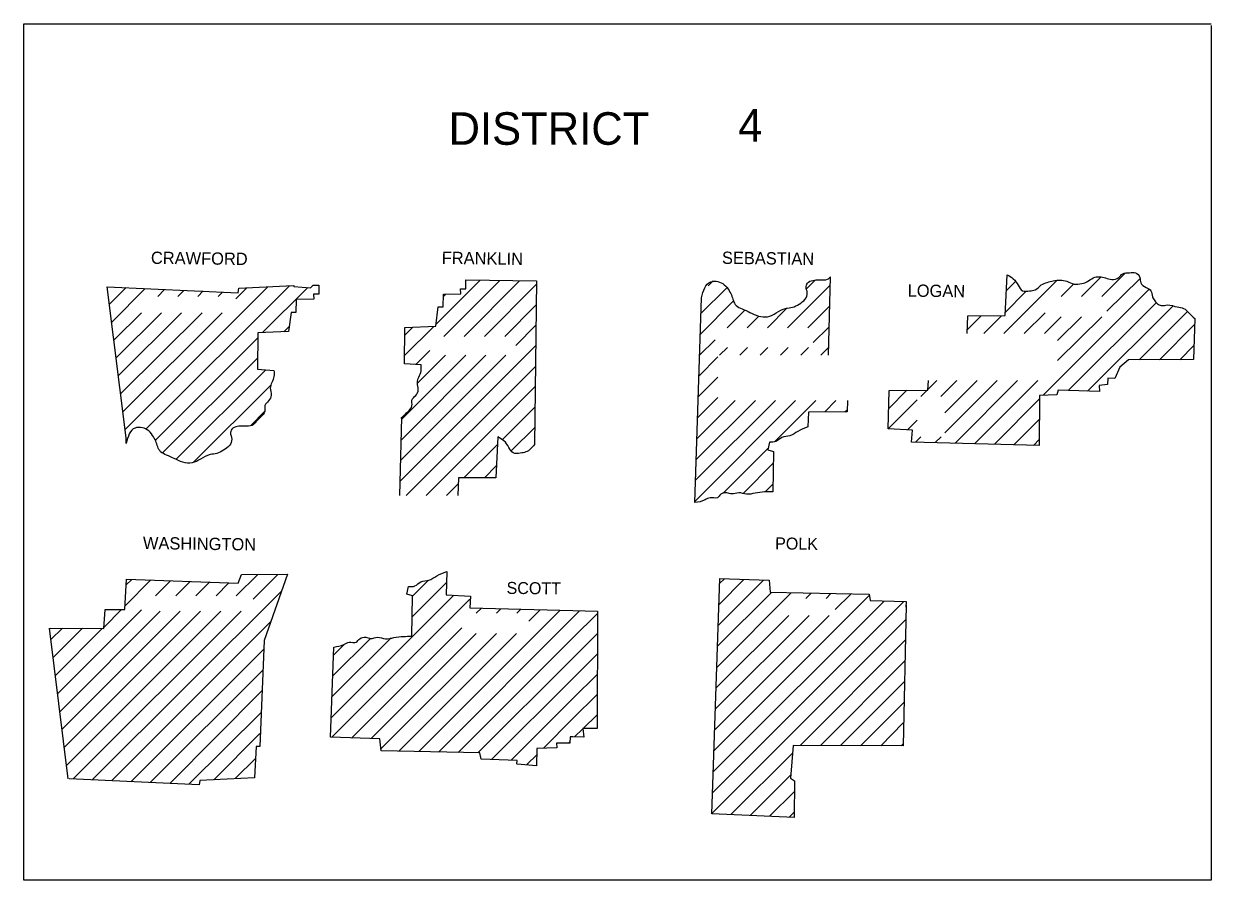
# Model space of a CAD drawing. Extents: x 21307 to 29830, y 1322443 to 1332359.
# Drawn here: x 27376.6 to 27792.3, y 1326512.9 to 1326812.9 of the extents above; entities that cross this region are included whole.
import ezdxf

# ---------------------------------------------------------------- set-up
doc = ezdxf.new("R2010")
doc.units = 0
doc.layers.add('R_Draft', color=7, linetype='Continuous')

msp = doc.modelspace()

# ---------------------------------------------------------------- linework, layer by layer
at = {"layer": 'R_Draft'}
msp.add_line((27792.32, 1326812.26), (27792.32, 1326512.86), dxfattribs=at)
for points in [[(27376.62, 1326512.86), (27376.62, 1326812.86), (27792.32, 1326812.86)], [(27658.92, 1326724.16), (27658.22, 1326696.76)], [(27706.82, 1326704.36), (27707.12, 1326710.56), (27720.12, 1326710.66), (27720.82, 1326724.96)], [(27746.92, 1326717.36), (27753.62, 1326724.06)], [(27754.02, 1326717.36), (27762.02, 1326725.36)], [(27755.82, 1326712.16), (27767.32, 1326723.56)], [(27405.82, 1326720.76), (27451.72, 1326718.66), (27451.92, 1326720.26), (27470.92, 1326721.16)], [(27412.42, 1326665.86), (27412.42, 1326667.86), (27405.82, 1326720.76)], [(27406.62, 1326714.66), (27412.42, 1326720.46)], [(27407.42, 1326708.36), (27419.12, 1326720.16)], [(27412.12, 1326670.76), (27462.12, 1326720.66)], [(27419.42, 1326670.96), (27469.62, 1326721.06)], [(27423.52, 1326717.36), (27425.92, 1326719.76)], [(27430.52, 1326717.36), (27432.62, 1326719.46)], [(27437.52, 1326717.36), (27439.42, 1326719.26)], [(27450.82, 1326716.46), (27454.62, 1326720.26)], [(27479.92, 1326721.26), (27479.92, 1326718.16), (27478.02, 1326718.16), (27478.12, 1326716.36), (27472.02, 1326716.26), (27471.92, 1326711.76), (27470.22, 1326711.76), (27469.32, 1326705.06), (27458.52, 1326704.56), (27458.42, 1326691.86), (27464.22, 1326691.46)], [(27460.22, 1326704.66), (27476.02, 1326720.46)], [(27471.12, 1326721.16), (27471.12, 1326720.86), (27477.02, 1326720.36), (27477.92, 1326721.26), (27479.92, 1326721.26)], [(27515.72, 1326693.36), (27509.92, 1326693.76), (27510.02, 1326706.46), (27520.82, 1326706.96), (27521.72, 1326713.66), (27523.42, 1326713.66), (27523.52, 1326718.16), (27529.62, 1326718.26), (27529.52, 1326720.06), (27531.42, 1326720.06), (27531.42, 1326723.16)], [(27520.92, 1326707.56), (27536.32, 1326722.96)], [(27523.72, 1326703.36), (27543.32, 1326722.96)], [(27530.82, 1326703.36), (27550.22, 1326722.76)], [(27531.42, 1326723.16), (27556.12, 1326722.76)], [(27537.92, 1326703.36), (27556.02, 1326721.56)], [(27556.12, 1326722.76), (27555.42, 1326665.46)], [(27613.52, 1326711.26), (27622.72, 1326720.36)], [(27616.22, 1326721.06), (27617.92, 1326722.76)], [(27644.02, 1326706.36), (27658.82, 1326721.16)], [(27650.62, 1326720.06), (27653.62, 1326723.06)], [(27719.72, 1326704.36), (27738.32, 1326722.96)], [(27720.52, 1326719.26), (27723.72, 1326722.46)], [(27733.52, 1326682.76), (27770.52, 1326719.76)], [(27739.82, 1326717.36), (27744.12, 1326721.66)], [(27444.72, 1326717.36), (27446.22, 1326718.86)], [(27523.42, 1326717.16), (27524.42, 1326718.16)], [(27611.52, 1326645.16), (27613.82, 1326716.86)], [(27613.42, 1326704.06), (27625.12, 1326715.76)], [(27720.12, 1326711.76), (27727.32, 1326718.96)], [(27742.22, 1326684.36), (27773.02, 1326715.16)], [(27408.22, 1326702.16), (27417.82, 1326711.66)], [(27409.02, 1326695.86), (27424.82, 1326711.66)], [(27409.72, 1326689.56), (27431.82, 1326711.66)], [(27410.52, 1326683.26), (27439.02, 1326711.66)], [(27411.32, 1326676.96), (27446.02, 1326711.66)], [(27545.02, 1326703.36), (27556.02, 1326714.36)], [(27622.82, 1326706.36), (27628.92, 1326712.46)], [(27636.92, 1326706.36), (27643.92, 1326713.36)], [(27651.12, 1326706.36), (27658.62, 1326713.86)], [(27726.82, 1326704.36), (27734.12, 1326711.66)], [(27749.02, 1326684.16), (27778.92, 1326713.96)], [(27767.12, 1326695.16), (27784.02, 1326712.06)], [(27467.62, 1326704.96), (27469.52, 1326706.86)], [(27509.92, 1326696.66), (27520.22, 1326706.86)], [(27509.92, 1326703.66), (27512.82, 1326706.56)], [(27548.82, 1326700.16), (27555.92, 1326707.26)], [(27629.82, 1326706.36), (27633.82, 1326710.36)], [(27653.02, 1326701.16), (27658.42, 1326706.56)], [(27706.92, 1326705.66), (27711.82, 1326710.56)], [(27712.72, 1326704.36), (27718.92, 1326710.56)], [(27786.52, 1326709.66), (27786.12, 1326695.26), (27763.32, 1326695.16), (27760.32, 1326692.56), (27758.62, 1326688.56), (27756.12, 1326688.76), (27756.02, 1326686.46), (27753.12, 1326686.16), (27753.22, 1326684.06), (27738.72, 1326684.46), (27738.22, 1326682.86), (27732.22, 1326682.66), (27732.12, 1326665.16)], [(27733.92, 1326704.36), (27739.82, 1326710.26)], [(27738.52, 1326694.86), (27754.02, 1326710.26)], [(27738.52, 1326701.86), (27746.92, 1326710.26)], [(27774.22, 1326695.16), (27786.42, 1326707.46)], [(27422.72, 1326667.06), (27458.52, 1326702.86)], [(27508.32, 1326652.56), (27555.82, 1326700.06)], [(27513.92, 1326693.56), (27518.72, 1326698.36)], [(27613.22, 1326696.76), (27618.62, 1326702.16)], [(27620.22, 1326696.76), (27622.92, 1326699.46)], [(27627.32, 1326696.76), (27630.02, 1326699.46)], [(27634.42, 1326696.76), (27637.12, 1326699.46)], [(27641.52, 1326696.76), (27644.22, 1326699.46)], [(27648.62, 1326696.76), (27651.32, 1326699.46)], [(27655.62, 1326696.76), (27658.22, 1326699.36)], [(27781.32, 1326695.16), (27786.22, 1326700.16)], [(27425.22, 1326662.56), (27458.52, 1326695.86)], [(27508.52, 1326659.86), (27545.42, 1326696.76)], [(27508.72, 1326667.06), (27538.42, 1326696.76)], [(27508.92, 1326674.36), (27531.32, 1326696.76)], [(27514.52, 1326687.06), (27524.22, 1326696.76)], [(27612.92, 1326689.46), (27619.62, 1326696.16)], [(27430.02, 1326660.36), (27461.42, 1326691.66)], [(27510.52, 1326647.66), (27555.72, 1326692.86)], [(27436.02, 1326659.26), (27463.12, 1326686.26)], [(27612.72, 1326682.16), (27619.62, 1326689.06)], [(27732.12, 1326665.16), (27687.42, 1326666.36), (27687.72, 1326670.46), (27679.22, 1326670.96), (27679.62, 1326684.36), (27693.12, 1326684.46), (27693.32, 1326687.86)], [(27693.22, 1326684.86), (27696.22, 1326687.86)], [(27697.62, 1326682.26), (27703.22, 1326687.86)], [(27699.02, 1326669.56), (27717.42, 1326687.86)], [(27699.02, 1326676.56), (27710.32, 1326687.86)], [(27702.62, 1326665.96), (27724.52, 1326687.86)], [(27709.42, 1326665.76), (27731.62, 1326687.86)], [(27517.52, 1326647.66), (27555.62, 1326685.76)], [(27612.52, 1326674.86), (27619.62, 1326681.96)], [(27679.52, 1326678.26), (27685.72, 1326684.46)], [(27690.62, 1326682.26), (27692.82, 1326684.46)], [(27544.32, 1326667.36), (27555.52, 1326678.56)], [(27611.62, 1326645.66), (27646.82, 1326680.86)], [(27611.82, 1326652.96), (27639.72, 1326680.86)], [(27612.02, 1326660.26), (27632.72, 1326680.86)], [(27612.22, 1326667.46), (27625.62, 1326680.86)], [(27639.42, 1326666.46), (27653.92, 1326680.86)], [(27665.02, 1326680.86), (27664.82, 1326676.96), (27651.32, 1326676.86), (27651.12, 1326671.66)], [(27657.02, 1326676.96), (27660.92, 1326680.86)], [(27664.02, 1326676.96), (27664.82, 1326677.66)], [(27679.22, 1326670.96), (27689.42, 1326681.16)], [(27716.42, 1326665.66), (27732.32, 1326681.56)], [(27456.12, 1326672.16), (27461.02, 1326677.16)], [(27508.22, 1326647.66), (27508.92, 1326674.96)], [(27686.02, 1326670.66), (27689.42, 1326674.06)], [(27723.22, 1326665.36), (27732.32, 1326674.46)], [(27547.32, 1326663.36), (27555.52, 1326671.46)], [(27542.52, 1326668.16), (27541.82, 1326653.86), (27528.82, 1326653.76), (27528.52, 1326647.66)], [(27530.72, 1326653.76), (27542.52, 1326665.56)], [(27637.72, 1326666.36), (27637.12, 1326663.66), (27639.12, 1326663.06), (27638.82, 1326648.96)], [(27688.82, 1326666.36), (27690.62, 1326668.16)], [(27695.62, 1326666.16), (27697.72, 1326668.16)], [(27730.12, 1326665.16), (27732.22, 1326667.36)], [(27621.42, 1326648.46), (27637.22, 1326664.26)], [(27537.92, 1326653.86), (27542.02, 1326658.06)], [(27628.42, 1326648.36), (27639.12, 1326659.06)], [(27524.62, 1326647.66), (27528.72, 1326651.76)], [(27636.12, 1326648.96), (27638.92, 1326651.76)], [(27385.92, 1326601.16), (27404.62, 1326601.06), (27405.12, 1326607.66), (27412.02, 1326607.66), (27412.62, 1326618.36), (27451.62, 1326616.96), (27452.82, 1326619.96), (27468.92, 1326620.06), (27460.82, 1326596.86), (27459.22, 1326559.76), (27458.02, 1326559.66), (27457.42, 1326548.76)], [(27451.02, 1326612.46), (27458.52, 1326619.96)], [(27456.92, 1326611.36), (27465.62, 1326619.96)], [(27524.72, 1326621.06), (27524.52, 1326612.86), (27533.02, 1326612.36), (27532.72, 1326608.26), (27568.82, 1326607.36)], [(27412.12, 1326608.96), (27421.12, 1326618.06)], [(27412.52, 1326616.36), (27414.42, 1326618.26)], [(27422.72, 1326612.46), (27428.02, 1326617.76)], [(27429.82, 1326612.46), (27434.82, 1326617.56)], [(27436.82, 1326612.46), (27441.72, 1326617.36)], [(27443.92, 1326612.46), (27448.42, 1326617.06)], [(27512.42, 1326598.36), (27512.72, 1326612.46), (27510.72, 1326613.06), (27511.32, 1326615.76)], [(27512.62, 1326612.26), (27518.22, 1326617.86)], [(27512.62, 1326605.16), (27524.62, 1326617.16)], [(27617.52, 1326536.16), (27620.32, 1326618.56)], [(27619.82, 1326602.26), (27635.52, 1326617.96)], [(27620.02, 1326609.46), (27628.72, 1326618.16)], [(27620.22, 1326618.56), (27637.52, 1326617.96), (27637.92, 1326613.76), (27672.52, 1326613.06), (27672.92, 1326610.86), (27685.52, 1326610.46), (27685.42, 1326608.56)], [(27620.22, 1326616.76), (27621.92, 1326618.46)], [(27400.62, 1326548.06), (27466.82, 1326614.16)], [(27484.22, 1326569.76), (27527.22, 1326612.66)], [(27484.52, 1326562.96), (27532.82, 1326611.26)], [(27618.32, 1326558.26), (27672.62, 1326612.56)], [(27619.32, 1326587.46), (27645.32, 1326613.56)], [(27619.52, 1326594.86), (27638.32, 1326613.66)], [(27650.42, 1326611.56), (27652.22, 1326613.36)], [(27657.52, 1326611.56), (27659.12, 1326613.26)], [(27660.62, 1326607.66), (27666.12, 1326613.06)], [(27388.52, 1326578.26), (27417.82, 1326607.56)], [(27389.32, 1326571.96), (27424.42, 1326607.06)], [(27390.12, 1326565.76), (27431.42, 1326607.06)], [(27390.92, 1326559.46), (27438.52, 1326607.06)], [(27391.72, 1326553.16), (27445.62, 1326607.06)], [(27393.92, 1326548.36), (27452.72, 1326607.06)], [(27404.72, 1326601.56), (27410.82, 1326607.66)], [(27514.92, 1326557.96), (27564.32, 1326607.36)], [(27535.02, 1326606.36), (27536.82, 1326608.16)], [(27542.12, 1326606.36), (27543.62, 1326607.96)], [(27549.22, 1326606.36), (27550.62, 1326607.76)], [(27553.42, 1326603.56), (27557.42, 1326607.56)], [(27568.82, 1326607.36), (27577.42, 1326607.06)], [(27568.82, 1326604.86), (27571.22, 1326607.26)], [(27577.42, 1326607.06), (27577.32, 1326566.06), (27572.32, 1326565.96), (27572.72, 1326562.96), (27568.82, 1326563.06)], [(27685.52, 1326609.16), (27684.42, 1326559.96), (27645.92, 1326560.06), (27645.02, 1326548.66), (27646.42, 1326547.66), (27646.32, 1326534.86), (27617.52, 1326536.16)], [(27617.82, 1326543.56), (27684.72, 1326610.46)], [(27618.12, 1326550.96), (27677.82, 1326610.66)], [(27407.42, 1326547.76), (27463.02, 1326603.36)], [(27521.82, 1326557.76), (27568.82, 1326604.86)], [(27568.82, 1326597.76), (27577.42, 1326606.26)], [(27617.62, 1326536.36), (27685.42, 1326604.16)], [(27618.52, 1326565.56), (27658.62, 1326605.56)], [(27618.82, 1326572.86), (27651.52, 1326605.56)], [(27619.02, 1326580.26), (27644.42, 1326605.56)], [(27392.22, 1326548.36), (27385.62, 1326601.16)], [(27386.12, 1326597.16), (27390.22, 1326601.16)], [(27386.92, 1326590.86), (27397.22, 1326601.16)], [(27387.72, 1326584.56), (27404.22, 1326601.16)], [(27491.42, 1326562.76), (27529.92, 1326601.26)], [(27498.22, 1326562.46), (27535.02, 1326599.26)], [(27501.72, 1326558.96), (27542.12, 1326599.26)], [(27508.02, 1326558.16), (27549.12, 1326599.26)], [(27568.82, 1326590.66), (27577.42, 1326599.26)], [(27484.02, 1326562.96), (27485.12, 1326594.56)], [(27484.52, 1326577.06), (27505.22, 1326597.76)], [(27484.82, 1326584.46), (27498.02, 1326597.56)], [(27485.12, 1326591.76), (27488.72, 1326595.36)], [(27528.72, 1326557.66), (27568.82, 1326597.76)], [(27648.42, 1326560.06), (27685.22, 1326596.96)], [(27414.12, 1326547.36), (27460.72, 1326593.86)], [(27535.62, 1326557.46), (27568.82, 1326590.66)], [(27568.82, 1326583.56), (27577.42, 1326592.16)], [(27420.92, 1326547.06), (27460.32, 1326586.46)], [(27655.52, 1326560.06), (27685.02, 1326589.66)], [(27540.52, 1326555.26), (27568.82, 1326583.56)], [(27568.82, 1326576.56), (27577.32, 1326584.96)], [(27662.52, 1326560.06), (27684.92, 1326582.46)], [(27427.72, 1326546.76), (27460.02, 1326579.16)], [(27568.82, 1326569.46), (27577.32, 1326577.96)], [(27547.22, 1326554.96), (27568.82, 1326576.56)], [(27669.52, 1326559.96), (27684.72, 1326575.16)], [(27434.42, 1326546.46), (27459.72, 1326571.66)], [(27558.62, 1326559.16), (27568.82, 1326569.46)], [(27572.42, 1326565.96), (27577.32, 1326570.86)], [(27569.42, 1326563.06), (27572.32, 1326565.86)], [(27676.62, 1326559.96), (27684.52, 1326567.96)], [(27443.12, 1326548.06), (27459.32, 1326564.26)], [(27549.22, 1326553.56), (27549.32, 1326554.86), (27536.72, 1326555.26), (27536.32, 1326557.46), (27501.72, 1326558.16), (27501.32, 1326562.36), (27484.02, 1326562.96)], [(27568.82, 1326563.06), (27567.92, 1326563.06), (27567.82, 1326560.86), (27563.12, 1326560.86), (27563.22, 1326559.26), (27556.22, 1326559.06), (27556.12, 1326552.96), (27549.32, 1326553.56)], [(27567.32, 1326560.86), (27567.82, 1326561.36)], [(27624.12, 1326535.86), (27645.72, 1326557.36)], [(27683.72, 1326559.96), (27684.42, 1326560.66)], [(27450.62, 1326548.56), (27457.82, 1326555.66)], [(27552.72, 1326553.36), (27556.22, 1326556.76)], [(27457.42, 1326548.76), (27438.22, 1326547.86), (27438.02, 1326546.26), (27392.52, 1326548.36)], [(27630.92, 1326535.56), (27645.12, 1326549.76)], [(27637.72, 1326535.26), (27646.42, 1326543.96)], [(27644.52, 1326534.96), (27646.42, 1326536.86)], [(27792.32, 1326512.86), (27376.62, 1326512.86)]]:
    msp.add_lwpolyline(points, dxfattribs=at)
for points in [[(27613.82, 1326716.86), (27617.12, 1326722.46), (27619.02, 1326722.66), (27621.32, 1326721.86), (27623.22, 1326719.86), (27624.32, 1326717.86), (27626.02, 1326714.16), (27628.12, 1326712.96), (27630.82, 1326711.76), (27633.82, 1326710.46), (27637.02, 1326710.26), (27640.02, 1326711.56), (27643.32, 1326713.16), (27645.72, 1326713.56), (27648.02, 1326714.66), (27650.12, 1326716.36), (27650.92, 1326718.56), (27650.52, 1326720.86), (27651.32, 1326722.36), (27653.42, 1326723.06), (27655.52, 1326723.16), (27658.02, 1326723.36), (27659.02, 1326724.26)], [(27720.82, 1326724.96), (27723.02, 1326723.56), (27724.72, 1326721.26), (27726.22, 1326719.36), (27728.72, 1326719.26), (27730.72, 1326719.66), (27732.82, 1326721.46)], [(27732.82, 1326721.46), (27737.02, 1326722.86), (27739.42, 1326723.06), (27741.82, 1326722.66), (27744.32, 1326721.66), (27747.02, 1326721.86), (27749.02, 1326722.56), (27751.02, 1326723.86), (27753.22, 1326724.26), (27755.32, 1326723.86), (27757.52, 1326723.26), (27759.92, 1326723.96), (27761.32, 1326725.26), (27763.72, 1326725.66), (27765.82, 1326725.66), (27767.32, 1326723.96), (27767.62, 1326722.16), (27769.52, 1326720.46), (27771.22, 1326719.36), (27771.72, 1326717.26), (27772.62, 1326715.76), (27773.52, 1326714.76), (27774.82, 1326714.16), (27777.02, 1326714.36), (27780.42, 1326713.66), (27782.62, 1326713.16), (27784.62, 1326711.46), (27786.52, 1326709.66)], [(27464.22, 1326691.46), (27464.22, 1326689.36), (27463.42, 1326687.16), (27462.92, 1326685.26), (27463.22, 1326682.76), (27462.32, 1326680.76), (27461.02, 1326679.16), (27461.02, 1326677.16), (27459.52, 1326675.06), (27457.92, 1326673.46), (27456.52, 1326672.16), (27454.02, 1326671.96), (27451.92, 1326671.86), (27449.82, 1326671.16), (27449.02, 1326669.66), (27449.42, 1326667.36), (27448.62, 1326665.16), (27446.52, 1326663.46), (27444.22, 1326662.36), (27441.82, 1326661.96), (27438.52, 1326660.36), (27435.52, 1326659.06), (27432.32, 1326659.26), (27429.32, 1326660.56), (27426.62, 1326661.76), (27424.52, 1326662.96), (27422.82, 1326666.66), (27421.72, 1326668.66), (27419.82, 1326670.66), (27417.52, 1326671.46), (27415.62, 1326671.26), (27412.42, 1326665.86)], [(27508.72, 1326674.76), (27509.42, 1326675.36), (27511.02, 1326676.96), (27512.52, 1326679.06), (27512.52, 1326681.06), (27513.82, 1326682.66), (27514.72, 1326684.66), (27514.42, 1326687.16), (27514.92, 1326689.06), (27515.72, 1326691.26), (27515.72, 1326693.36)], [(27651.12, 1326671.66), (27647.62, 1326670.06), (27644.82, 1326668.56), (27642.02, 1326667.96), (27639.92, 1326666.56), (27637.72, 1326666.36)], [(27555.42, 1326665.46), (27552.42, 1326662.86), (27550.42, 1326662.46), (27547.92, 1326662.56), (27546.42, 1326664.46), (27544.72, 1326666.76), (27542.52, 1326668.16)], [(27638.82, 1326648.96), (27635.92, 1326648.86), (27632.62, 1326648.46), (27629.62, 1326648.06), (27626.92, 1326648.56), (27624.42, 1326648.16), (27622.72, 1326648.56), (27620.62, 1326648.06), (27619.42, 1326646.86), (27616.92, 1326646.86), (27615.12, 1326646.06), (27611.52, 1326645.16)], [(27511.32, 1326615.76), (27513.52, 1326615.96), (27515.62, 1326617.36), (27518.42, 1326617.96), (27521.22, 1326619.46), (27524.72, 1326621.06)], [(27485.12, 1326594.56), (27488.72, 1326595.46), (27490.52, 1326596.26), (27493.02, 1326596.26), (27494.22, 1326597.46), (27496.32, 1326597.96), (27498.02, 1326597.56), (27500.52, 1326597.96), (27503.22, 1326597.46), (27506.22, 1326597.86), (27509.52, 1326598.26), (27512.42, 1326598.36)]]:
    msp.add_spline(points, degree=3, dxfattribs=at)

# ---------------------------------------------------------------- texts
for s, p in [('DISTRICT', (27525.32, 1326770.46)), ('4', (27626.72, 1326771.56))]:
    msp.add_text(s, height=11.4, dxfattribs=at).set_placement(p)
for s, height, rotation, p in [('CRAWFORD', 4.3, 359.2771, (27421.12, 1326728.76)), ('FRANKLIN', 4.301, 359.1815, (27522.92, 1326728.76)), ('SEBASTIAN', 4.3, 359.2816, (27621.02, 1326728.76)), ('LOGAN', 4.301, 359.3969, (27686.02, 1326717.26)), ('WASHINGTON', 4.3, 359.232, (27418.32, 1326628.86)), ('POLK', 4.199, 359.2152, (27639.62, 1326628.76)), ('SCOTT', 4.201, 359.4063, (27545.62, 1326613.16))]:
    msp.add_text(s, height=height, rotation=rotation, dxfattribs=at).set_placement(p)

doc.saveas('drawing.dxf')
